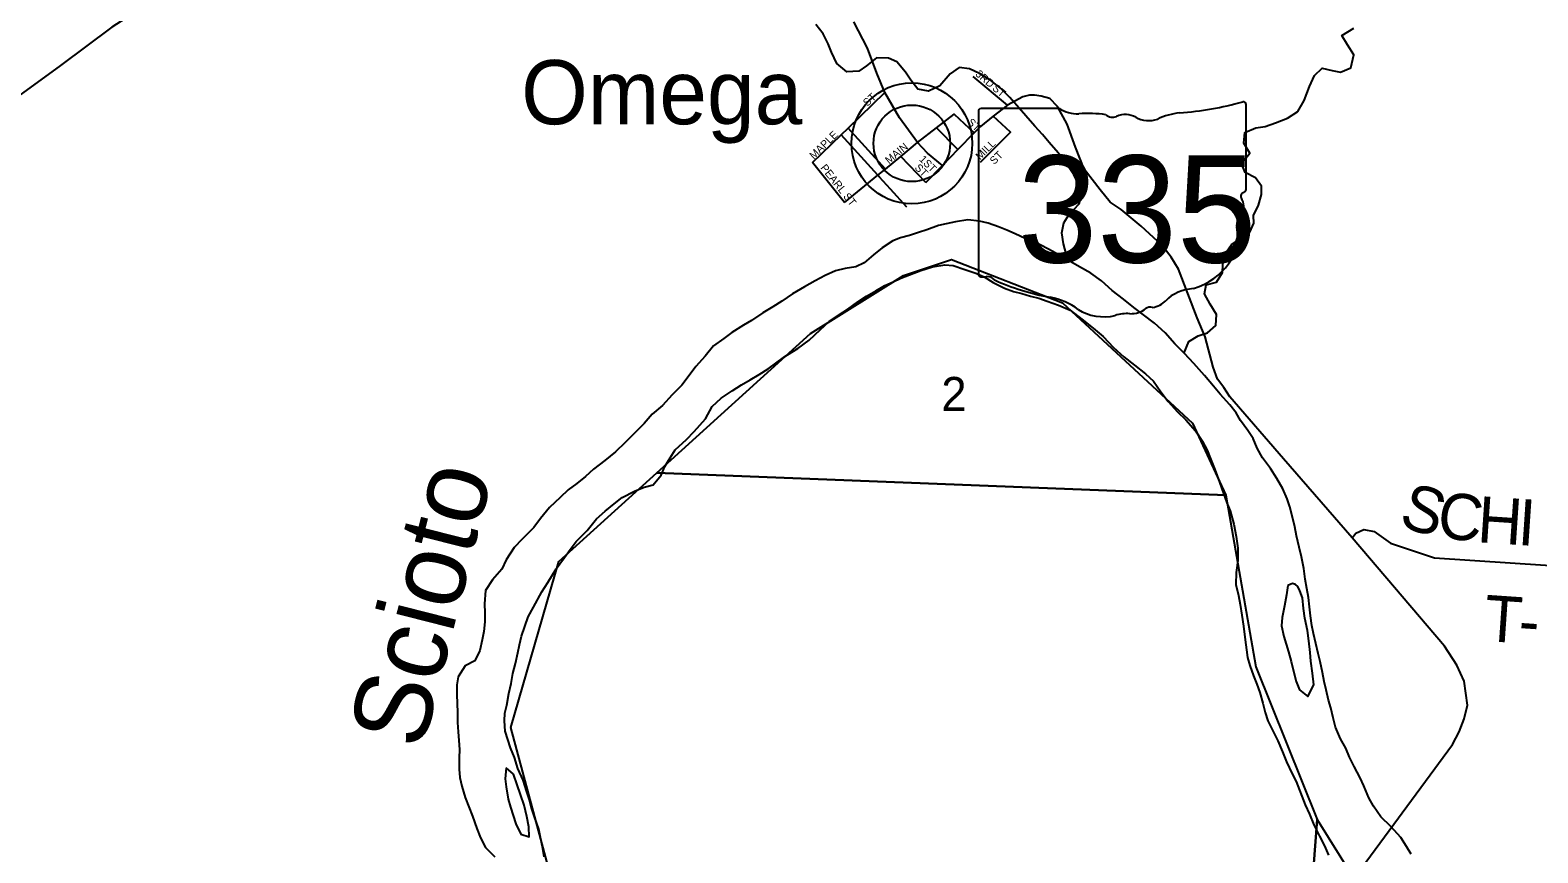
# Model space of a CAD drawing. Extents: x 1578669 to 1989827, y 208020 to 553079.
# Drawn here: x 1846418 to 1856224, y 415109 to 420455 of the extents above; entities that cross this region are included whole.
import ezdxf

# ---------------------------------------------------------------- set-up
doc = ezdxf.new("R2010")
doc.units = 0
for name, color, linetype in [('GM_X_Major_River', 7, 'Continuous'), ('GM_X_Major_River_Text', 7, 'Continuous'), ('GM_X_Minor_River', 7, 'Continuous'), ('GM_X_Section', 7, 'Continuous'), ('GM_X_Section_Text', 7, 'Continuous'), ('GM_X_State_Location', 7, 'Continuous'), ('GM_X_State_Route', 7, 'Continuous'), ('GM_X_State_Shield', 7, 'Continuous'), ('GM_X_Township_Road', 7, 'Continuous'), ('GM_X_Township_Road_Text', 7, 'Continuous'), ('GM_X_Township_Subdivision', 7, 'Continuous'), ('GM_X_Township_Subdivision_Text', 7, 'Continuous'), ('GM_X_Unincorporated', 7, 'Continuous'), ('GM_X_Unincorporated_Location', 7, 'Continuous'), ('GM_X_Unincorporated_Text', 7, 'Continuous')]:
    doc.layers.add(name, color=color, linetype=linetype)

msp = doc.modelspace()

# ---------------------------------------------------------------- linework, layer by layer
at = {"layer": 'GM_X_Major_River'}
for points in [[(1855400.7, 415099.2), (1855369.2, 415149.6), (1855331.9, 415208), (1855266.8, 415278.8), (1855201.5, 415341.6), (1855154.4, 415412.2), (1855125, 415466.6), (1855091.8, 415543), (1855068.4, 415595.3), (1855029.3, 415669.8), (1854998, 415730.3), (1854974.6, 415788.6), (1854941.3, 415849), (1854908.2, 415925.5), (1854892.9, 415985.7), (1854877.6, 416049.9), (1854862.1, 416100.1), (1854846.9, 416168.4), (1854833.5, 416222.6), (1854824.1, 416280.7), (1854808.9, 416353), (1854795.5, 416403.1), (1854780.2, 416469.4), (1854764.9, 416533.6), (1854753.5, 416585.8), (1854744.2, 416650), (1854738.8, 416708.1), (1854731.5, 416768.2), (1854722.1, 416826.4), (1854710.8, 416886.5), (1854701.6, 416956.7), (1854686.4, 417033), (1854671.1, 417095.2), (1854653.9, 417169.5), (1854642.6, 417227.6), (1854629.2, 417281.8), (1854610, 417358.1), (1854592.6, 417408.4), (1854565.3, 417474.7), (1854526.1, 417541.2), (1854484.8, 417605.8), (1854433.7, 417676.4), (1854398.4, 417738.8), (1854373.1, 417801.2), (1854337.7, 417853.6), (1854290.5, 417918.2), (1854261.1, 417968.6), (1854219.7, 418021.1), (1854158.5, 418089.9), (1854115.1, 418142.4), (1854055.9, 418211.1), (1853986.9, 418290), (1853925.7, 418354.7), (1853862.4, 418417.5), (1853799.3, 418488.3), (1853730.1, 418551.1), (1853658.8, 418606), (1853595.4, 418652.7), (1853528, 418707.5), (1853454.7, 418762.4), (1853385.5, 418827.2), (1853316.1, 418876.1), (1853242.7, 418916.9), (1853187.1, 418949.6), (1853121.6, 418986.4), (1853070, 419017), (1852958.8, 419074.3), (1852889.2, 419101.1), (1852823.6, 419131.8), (1852769.9, 419156.5), (1852716.2, 419177.1), (1852648.6, 419201.9), (1852592.8, 419214.5), (1852517, 419223.4), (1852437, 419210.2), (1852374.9, 419196.9), (1852324.9, 419185.5), (1852250.7, 419158.3), (1852196.6, 419140.9), (1852136.5, 419121.5), (1852078.4, 419106.2), (1852028.3, 419086.7), (1851959.9, 419041.5), (1851903.5, 418996), (1851843, 418942.7), (1851788.8, 418917.2), (1851718.7, 418906)], [(1851718.7, 418906), (1851656.7, 418890.7), (1851588.5, 418861.5), (1851524.2, 418826.1), (1851453.8, 418786.9), (1851375.5, 418741.7), (1851307, 418694.5), (1851248.7, 418657.1), (1851184.4, 418617.8), (1851110, 418568.5), (1851057.7, 418537.1), (1850981.3, 418489.9), (1850929, 418452.5), (1850862.5, 418403.2), (1850807.9, 418335.7), (1850747.3, 418270.3), (1850710.8, 418218.7), (1850656.1, 418147.2), (1850593.5, 418085.9), (1850530.9, 418016.5), (1850464.3, 417959.2), (1850411.8, 417899.7), (1850339.1, 417828.5), (1850288.6, 417775), (1850226.1, 417715.7), (1850155.5, 417658.4), (1850083, 417601.2), (1850030.6, 417553.7), (1849974.2, 417508.3), (1849917.8, 417466.9), (1849865.4, 417417.4), (1849796.8, 417352.1), (1849738.1, 417280.7), (1849693.5, 417223.2), (1849618.8, 417147.9), (1849566.3, 417092.5), (1849513.5, 417013), (1849484.9, 416953.2), (1849424.2, 416881.9), (1849379.6, 416814.3), (1849372.6, 416726.3), (1849376, 416668.2), (1849375.4, 416610.2), (1849368.7, 416546.2), (1849358.1, 416492.2), (1849343.4, 416424.3), (1849310.7, 416356.6), (1849248.5, 416323.3), (1849201.8, 416251.8), (1849193.2, 416199.8), (1849192.5, 416135.8), (1849195.9, 416081.7), (1849197.3, 416017.6), (1849198.6, 415955.5), (1849201.9, 415895.4), (1849205.3, 415839.3), (1849210.7, 415781.2), (1849208.1, 415725.2), (1849209.3, 415653.1), (1849212.7, 415599), (1849226.1, 415540.8), (1849247.3, 415468.5), (1849270.6, 415408.2), (1849295.9, 415345.9), (1849323, 415267.5), (1849346.3, 415205.2), (1849379.6, 415142.8), (1849440.9, 415082)], [(1851268.8, 418290.5), (1851327.1, 418333.9), (1851411.6, 418387), (1851484.1, 418440.2), (1851556.7, 418507.5), (1851615.2, 418560.9), (1851681.6, 418608.2), (1851735.9, 418641.6), (1851800.3, 418688.9), (1851858.6, 418726.3), (1851918.9, 418761.6), (1851977.2, 418795), (1852031.4, 418820.4), (1852081.6, 418843.9), (1852137.7, 418865.3), (1852209.9, 418892.5), (1852286.1, 418917.7), (1852366.1, 418930.8), (1852422, 418926.2), (1852497.6, 418899.3), (1852569.2, 418876.5), (1852622.9, 418851.8), (1852682.4, 418815.1), (1852755.9, 418778.3), (1852813.6, 418757.6), (1852867.3, 418743), (1852923.1, 418726.3), (1852978.9, 418713.7), (1853032.6, 418695.1), (1853106.2, 418668.2), (1853181.8, 418635.3), (1853259, 418576.4), (1853332.3, 418519.5), (1853397.6, 418464.8), (1853464.7, 418391.9), (1853532, 418333.1), (1853601.3, 418278.3), (1853672.6, 418221.5), (1853724, 418174.8), (1853771.2, 418104.2), (1853820.5, 418041.6), (1853879.7, 417974.9), (1853935, 417922.2), (1853998.2, 417851.4), (1854043.4, 417782.9), (1854072.7, 417726.5), (1854092.1, 417676.2), (1854123.3, 417599.8), (1854152.4, 417517.4), (1854179.5, 417443), (1854200.8, 417382.7), (1854222.3, 417330.4), (1854247.3, 417244.1), (1854262.4, 417163.8), (1854271.6, 417089.7), (1854272.7, 417007.6), (1854261.9, 416929.6), (1854259.1, 416853.6), (1854276.3, 416781.3), (1854287.6, 416723.1), (1854298.9, 416653), (1854310.1, 416580.8), (1854317.3, 416510.6), (1854335.9, 416378.3), (1854351.3, 416326.1), (1854374.5, 416259.7), (1854395.9, 416205.5), (1854415.3, 416151.2), (1854434.5, 416080.9), (1854449.9, 416020.7), (1854467.3, 415966.4), (1854506.4, 415887.9), (1854531.8, 415835.6), (1854563, 415765.2), (1854588.2, 415700.8), (1854625.4, 415622.3), (1854652.8, 415572), (1854711.1, 415421.2), (1854738.4, 415360.8), (1854767.6, 415290.4), (1854802.7, 415216), (1854836, 415153.5), (1854861.3, 415093.2)], [(1849760.4, 415082.4), (1849751.1, 415146.6), (1849739.7, 415196.8), (1849726.4, 415263), (1849697.3, 415343.4), (1849681.9, 415395.6), (1849666.5, 415453.8), (1849649.1, 415506.1), (1849623.9, 415580.4), (1849590.8, 415656.9), (1849567.6, 415729.2), (1849542.3, 415791.5), (1849507.6, 415900), (1849502.3, 415966.1), (1849504.8, 416016.2), (1849519.3, 416068), (1849532.1, 416144), (1849546.8, 416209.9), (1849557.5, 416273.8), (1849574.2, 416339.7), (1849590.9, 416407.6), (1849601.4, 416459.5), (1849614, 416517.4), (1849657.3, 416643), (1849691.9, 416704.7), (1849746.9, 416804.2), (1849785.5, 416865.8), (1849838.4, 416955.3), (1849893.1, 417028.8), (1849929.6, 417080.4), (1849970.1, 417132), (1850040.8, 417203.2), (1850101.5, 417278.6), (1850158, 417330.1), (1850216.4, 417377.5), (1850268.8, 417418.9), (1850349.1, 417460), (1850411.3, 417485.4), (1850469.4, 417500.7), (1850522, 417562.2), (1850546.6, 417620), (1850581.1, 417675.6), (1850613.6, 417727.3), (1850686.3, 417794.6), (1850736.8, 417848), (1850809.5, 417929.3), (1850854.3, 418008.9), (1850912.8, 418064.3), (1850983.2, 418111.5), (1851043.6, 418150.9), (1851101.8, 418182.3), (1851160.1, 418217.6), (1851218.4, 418255), (1851268.8, 418290.5)], [(1854597, 416846.9), (1854588.3, 416784.9), (1854575.5, 416714.9), (1854560.6, 416638.9), (1854556, 416584.9), (1854571.2, 416514.5), (1854602.1, 416414), (1854619.4, 416351.7), (1854634.7, 416289.4), (1854651.9, 416223.1), (1854673.3, 416168.7), (1854726.8, 416124), (1854767.7, 416199.7), (1854758.6, 416276), (1854747.5, 416354.2), (1854742.1, 416410.4), (1854735, 416486.6), (1854725.7, 416552.8), (1854708.6, 416633.2), (1854699.3, 416697.4), (1854694.1, 416765.6)], [(1854694.1, 416765.6), (1854674.7, 416811), (1854663.2, 416838.6), (1854647.1, 416852.4), (1854628.8, 416859.3), (1854597, 416846.9)], [(1849513.2, 415661.2), (1849508.4, 415589.1), (1849513.8, 415537), (1849526.9, 415456.7), (1849542.3, 415406.4), (1849577.1, 415297.8), (1849610.3, 415229.3), (1849664.1, 415212.6), (1849660.9, 415276.8), (1849647.6, 415345.1), (1849630.5, 415417.4), (1849607.2, 415487.8), (1849585.9, 415550.2), (1849562.7, 415620.6)], [(1849562.7, 415620.6), (1849513.2, 415661.2)]]:
    msp.add_lwpolyline(points, dxfattribs=at)
at = {"layer": 'GM_X_Minor_River'}
for points in [[(1853166.6, 418961.1), (1853139.6, 419066), (1853128.4, 419138.2), (1853141.2, 419204.2), (1853173.8, 419255.9), (1853240.7, 419327.3), (1853259.4, 419395.2), (1853242, 419445.5), (1853206.8, 419516.1), (1853163.5, 419580.7), (1853104.4, 419657.5), (1853045.1, 419726.3), (1853001.7, 419776.9), (1852952.3, 419831.6), (1852893, 419898.4), (1852849.6, 419949), (1852790.4, 420017.8), (1852729, 420078.7), (1852663.6, 420131.5), (1852592.1, 420174.5), (1852526.4, 420203.2), (1852460.4, 420212), (1852402, 420172.6), (1852335, 420093.2), (1852260.6, 420058), (1852190.7, 420072.9), (1852145.3, 420129.5), (1852111.9, 420182), (1852054.7, 420248.8), (1852000.9, 420273.5), (1851922.9, 420276.4), (1851858.3, 420223), (1851807.9, 420189.5), (1851729.8, 420184.4), (1851664.4, 420239.3), (1851629.2, 420311.8), (1851607.8, 420366.2), (1851576.6, 420430.7), (1851527.3, 420493.3)], [(1853922.6, 418357.8), (1853954.7, 418431.3), (1854015.2, 418468.7), (1854075.5, 418488.1), (1854130, 418535.5), (1854134.8, 418607.6), (1854091.6, 418674.2), (1854056.3, 418740.8), (1854067, 418800.8), (1854133.2, 418818), (1854172, 418879.7), (1854174.5, 418929.8), (1854185.3, 418997.8), (1854232.1, 419063.4), (1854296.6, 419104.7), (1854351, 419142.1), (1854375.7, 419200), (1854374.3, 419250.1), (1854407.1, 419317.8), (1854425.9, 419387.8), (1854426.5, 419441.9), (1854387.1, 419496.4), (1854319.4, 419529.3), (1854296.1, 419589.6), (1854350.9, 419655.1), (1854311.6, 419721.7), (1854318.4, 419789.8), (1854388.8, 419821), (1854450.9, 419830.3), (1854517.2, 419853.6), (1854595.6, 419882.8), (1854662.1, 419926.1), (1854705, 419997.7), (1854738, 420089.5), (1854770.9, 420161.3), (1854821.4, 420208.8), (1854885.3, 420194), (1854939.2, 420181.4), (1855007.5, 420210.6), (1855026.5, 420294.6), (1854985.2, 420359.2), (1854949.9, 420421.7), (1855026.5, 420468.9)]]:
    msp.add_lwpolyline(points, dxfattribs=at)
at = {"layer": 'GM_X_Section'}
for points in [[(1850494, 417579), (1851492.3, 418484.2), (1852098.2, 418861.3), (1852410.7, 418963.8), (1853131.3, 418682.3), (1853977.6, 417900.2), (1854195.3, 417433.2)], [(1850494, 417579), (1854195.3, 417433.2), (1854390, 416318.2), (1854789.2, 415324.2), (1854552.2, 412211.3), (1850293.3, 412477.9), (1850282.7, 414010), (1849817, 414906.2), (1849544, 415923.6), (1849857.2, 417002.1)], [(1859898.7, 416784.5), (1860341.9, 416743.2), (1859899.5, 411619.5), (1854760.1, 412198.4), (1854552.2, 412211.3), (1854789.2, 415324.2), (1855311.2, 414487.7), (1855701.7, 414187.8), (1855988.2, 414257.9), (1857049.4, 414517.3), (1858566.6, 415166), (1859604.9, 416483.1)]]:
    msp.add_lwpolyline(points, close=True, dxfattribs=at)
at = {"layer": 'GM_X_State_Route'}
for points in [[(1850430.2, 422420.8), (1850379.4, 422416.2), (1850155.7, 422396), (1850077.5, 422385.8), (1849963.4, 422361.4), (1849703.2, 422242.4), (1849437, 422099.3), (1849339, 422050.9), (1849050.8, 421877.6), (1847760.6, 420997.8), (1846950.4, 420474.2), (1846616.4, 420224.7), (1846344.4, 420029.4)], [(1854570.1, 417669.7), (1854220.7, 418071.7), (1854180.4, 418133.8), (1854140.2, 418187.8), (1854111.9, 418265.9), (1854059.2, 418462.3), (1854008.7, 418586.5), (1853887.5, 418903), (1853839.2, 418981), (1853778.8, 419057.1), (1853644.2, 419181), (1853513.6, 419288.9), (1853443.3, 419336.9), (1853376.9, 419416.9), (1853272.3, 419553), (1853217.8, 419695.2), (1853163.3, 419843.4), (1853098.8, 419959.6), (1853050.5, 420011.6), (1852994.4, 420027.4), (1852950.2, 420033.3), (1852918.2, 420033.2), (1852874.1, 420023.1), (1852773.8, 419968), (1852681.7, 419896.8), (1852598.1, 419829.9), (1852557.5, 419788.1), (1852451.9, 419679.2), (1852352.3, 419576.6), (1852253.9, 419656.5), (1852189.8, 419724.5), (1852072.8, 419886.6), (1851976.3, 420050.4), (1851925.7, 420174.9), (1851863.1, 420339.2), (1851774.4, 420509.4)], [(1854544.3, 413713.6), (1854536, 413763.6), (1854527.5, 413950.1), (1854546.8, 414164.7), (1854608.5, 414333.3), (1854694.2, 414487.9), (1854754.1, 414570.3), (1855668.4, 415811.9), (1855712.2, 415894.2), (1855744.1, 415980.5), (1855765.8, 416068.8), (1855745.4, 416225.2), (1855696.9, 416329.3), (1855616.4, 416451.4), (1855017, 417155.5), (1854570.1, 417669.7)]]:
    msp.add_lwpolyline(points, dxfattribs=at)
at = {"layer": 'GM_X_State_Shield'}
for p, q in [((1854325.9, 419418.9), (1854325.9, 419971.6)), ((1852585.7, 419927.2), (1852585.7, 418870.6)), ((1853112.5, 419945.4), (1852602.9, 419945.4)), ((1854325.8, 419419), (1854325.9, 419418.9))]:
    msp.add_line(p, q, dxfattribs=at)
for centre, major_axis, start_param, end_param in [((1853706, 421386), (1845.5, 0), 4.814394, 5.042369), ((1854306.6, 419973.9), (19.4, 0), 6.141152, 7.989035), ((1852605.7, 419929.5), (20.2, 0), 1.712693, 3.28349), ((1853233.9, 420068.1), (195.5, 0), 4.042523, 4.731795), ((1853298.7, 419352.2), (702, 0), 1.404758, 1.657858), ((1853458.1, 419935), (56.4, 0), 3.836095, 5.185415), ((1853540.9, 419812.8), (117.3, 0), 0.950623, 2.079405), ((1853692.3, 419980.3), (141.1, 0), 4.081561, 5.145723), ((1853941.4, 419622.7), (371.3, 0), 1.699011, 2.107814), ((1854321.5, 419378.3), (30, 0), 1.883978, 3.671073), ((1854305.3, 419416.7), (20.7, 0), 5.05454, 6.418171), ((1854130.7, 419308.4), (180, 0), 5.934695, 6.695948), ((1854395.3, 419187.5), (130.9, 0), 2.387724, 3.262537), ((1853809.4, 419117.2), (461.6, 0), 5.101752, 6.440018), ((1852605.8, 418868.3), (20.3, 0), 3.00124, 4.508301), ((1852608.9, 418976.4), (155.2, 0), 4.665946, 4.897461), ((1852640.7, 418809.6), (56, 0), 0.519207, 1.627899), ((1853347.3, 419759), (1332.7, 0), 4.195997, 4.488961), ((1852950, 418395.9), (417, 0), 0.823519, 1.323587), ((1853683.8, 418768.2), (149.1, 0), 4.937069, 5.64225), ((1854004.1, 418573.9), (252.8, 0), 1.647645, 2.488434), ((1853400.9, 418804.4), (264.6, 0), 4.026481, 4.996735), ((1853553.8, 418439.1), (217.4, 0), 1.495662, 1.94098), ((1853573.2, 418725.3), (141, 0), 4.691044, 5.507374), ((1853700.7, 418622.9), (39.7, 0), 1.147584, 2.315152)]:
    msp.add_ellipse(centre, major_axis=major_axis, ratio=0.8, start_param=start_param, end_param=end_param, dxfattribs=at)
at = {"layer": 'GM_X_Township_Road'}
msp.add_lwpolyline([(1855017, 417155.5), (1855040.9, 417185.5), (1855093, 417209.2), (1855159, 417196.8), (1855264.5, 417122.1), (1855551.9, 417026.2), (1856535.5, 416960.4), (1857563.3, 416952.5), (1859217.3, 416973), (1859315.4, 416978.4), (1859503.7, 417045.5), (1861957.4, 418720.6), (1862410.9, 418992.5), (1862927.2, 419390.3), (1863615.6, 419805.2), (1863854.5, 419962.1), (1863976.9, 420029.5), (1864099.2, 420076.9), (1864215.8, 420176.5), (1864294.5, 420292.2), (1864310.9, 420372.3), (1864299.3, 420436.5)], dxfattribs=at)
at = {"layer": 'GM_X_Township_Subdivision'}
for points in [[(1852773.8, 419968), (1852551.2, 420154.2)], [(1851507.3, 419595.5), (1851692.4, 419775), (1851737.7, 419819), (1851976.3, 420050.4)], [(1852189.8, 419724.5), (1852312.5, 419820.2), (1852428.1, 419910.4), (1852557.5, 419788.1)], [(1852599.1, 419597.9), (1852794, 419791.8), (1852681.7, 419896.8)], [(1851942.3, 419501), (1851931.7, 419512.7), (1851692.4, 419775)], [(1851980.5, 419552.8), (1851737.7, 419819)], [(1852451.9, 419679.2), (1852312.5, 419820.2)], [(1851714.9, 419334.8), (1851931.7, 419512.7), (1851980.5, 419552.8), (1852080.7, 419635), (1852189.8, 419724.5)], [(1851714.9, 419334.8), (1851507.3, 419595.5)], [(1852243.1, 419466.3), (1852080.7, 419635)], [(1852243.1, 419466.3), (1852352.3, 419576.6)], [(1852013.7, 419422.7), (1851942.3, 419501), (1851942.3, 419501)], [(1852120.8, 419305.3), (1852013.7, 419422.7), (1852013.7, 419422.7)]]:
    msp.add_lwpolyline(points, dxfattribs=at)
at = {"layer": 'GM_X_Unincorporated'}
for radius in [392.8, 249]:
    msp.add_circle((1852152.4, 419719.8), radius, dxfattribs=at)
at = {"layer": 'GM_X_Unincorporated_Location'}
msp.add_line((1852152.4, 419719.8), (1852152.4, 419719.8), dxfattribs=at)

# ---------------------------------------------------------------- texts
at = {"layer": 'GM_X_Major_River_Text'}
msp.add_text('Scioto', height=500.06, rotation=75.76691, dxfattribs=at).set_placement((1848970, 415767.2))
at = {"layer": 'GM_X_Section_Text'}
msp.add_text('2', height=221, rotation=0.00001, dxfattribs=at).set_placement((1852344.1, 417980.4))
at = {"layer": 'GM_X_State_Location'}
for s in ['s', 'r']:
    msp.add_text(s, height=1, dxfattribs=at).set_placement((1853436.3, 419328.7))
msp.add_text('335', height=1, rotation=0.00001, dxfattribs=at).set_placement((1853083.3, 419255.9))
at = {"layer": 'GM_X_State_Shield'}
msp.add_text('335', height=696.1, dxfattribs=at).set_placement((1852840.9, 418945.1))
at = {"layer": 'GM_X_Township_Road_Text'}
for s, rotation, p in [('S', 342.49518, (1855310.3, 417235.8)), ('C', 352.43674, (1855558.8, 417162.6)), ('H', 356.17172, (1855824.3, 417128)), ('I', 356.17243, (1856087.7, 417110.4)), ('T', 356.0414, (1855867.6, 416486.6)), ('-', 356.15583, (1856092.1, 416471))]:
    msp.add_text(s, height=300, rotation=rotation, dxfattribs=at).set_placement(p)
at = {"layer": 'GM_X_Township_Subdivision_Text'}
for s, rotation, p in [('3RD', 319.62722, (1852561.4, 420163.6)), ('ST', 320.19085, (1852671.3, 420071.2)), ('ST', 42.50219, (1851862.5, 419956.5)), ('ST', 317.49781, (1852508.8, 419850.9)), ('MAPLE', 44.14207, (1851514.7, 419613.2)), ('MAIN', 39.61099, (1852003.8, 419583)), ('MILL', 44.99544, (1852597, 419608.7)), ('ST', 44.99089, (1852688.6, 419578.6)), ('PEARL ST', 308.51537, (1851555, 419559.5)), ('ST', 315, (1852167.2, 419557.2)), ('1ST', 315, (1852196.2, 419612.5))]:
    msp.add_text(s, height=50, rotation=rotation, dxfattribs=at).set_placement(p)
at = {"layer": 'GM_X_Unincorporated_Text'}
msp.add_text('Omega', height=417, rotation=0.00001, dxfattribs=at).set_placement((1849611.7, 419843.8))

doc.saveas('drawing.dxf')
